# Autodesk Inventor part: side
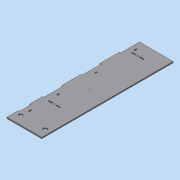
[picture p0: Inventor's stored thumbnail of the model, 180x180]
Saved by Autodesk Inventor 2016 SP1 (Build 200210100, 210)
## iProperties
Created: 2016-06
Part Number: side
Material: Generic
Document SubType Name: Modeling
Designer: Mohamed A.
Density: 1 g/cm^3
Appearance: Default
d0: 85.000 mm
d1: 320.000 mm
d2: 3.000 mm
d3: 0.00 deg
d6: 3.000 mm
d4: 233.000 mm
Author: Mohamed A.
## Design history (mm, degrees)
sketch "Sketch1"
  geometry: L1 (-42.5, 160)-(42.5, 160); L2 (42.5, 160)-(42.5, -160); L3 (42.5, -160)-(-42.5, -160); L4 (-42.5, -160)-(-42.5, 160); L5 (-42.5, 160)-(42.5, -160); L6 (42.5, 160)-(-42.5, -160); 1 further point
  constraints: 12 end point, 2 midpoint, 2 parallel, 1 horizontal, 1 perpendicular
  dimensions: "d0" = 85 distance of L2.end L3.end; "d1" = 320 distance of L1.end L2.end
extrude "Extrusion1" new body sketch "Sketch1" distance "d2" = 3; taper "d3" = 0 deg
sketch "Sketch2"
  geometry: L1 (-26.505, -73)-(-16.505, -73) reference; L2 (-7.505, -76)-(2.495, -76) reference; L3 (42.5, 160)-(-42.5, 160) reference; L4 (-42.5, 113.4)-(-39.5, 113.4); L5 (-39.5, 113.4)-(-39.5, 160); L6 (-42.5, 66.8)-(-39.5, 66.8); L7 (-39.5, 66.8)-(-39.5, 20.2); L8 (-39.5, 20.2)-(-42.5, 20.2); L9 (-39.5, -26.4)-(-42.5, -26.4); L10 (-42.5, -26.4)-(-42.5, -73); L11 (-39.5, 160)-(-42.5, 160); L12 (-42.5, 113.4)-(-42.5, 160); L13 (-42.5, 66.8)-(-42.5, 20.2); L14 (-39.5, -26.4)-(-39.5, -73); L15 (-42.5, -73)-(-39.5, -73); L16 (-42.5, -104)-(-39.5, -104); L17 (-39.5, -104)-(-39.5, -132); L18 (-39.5, -132)-(-42.5, -132); L19 (-42.5, -132)-(-42.5, -104); L20 (-42.5, -160)-(42.5, -160) reference; 1 further point; 1 other entity
  constraints: 32 end point, 6 perpendicular, 5 horizontal, 3 parallel, 2 point on line, 2 vertical, 1 collinear, 2 other
  dimensions: "d4" = 233 distance from line of L3 L1.start (derived); "d6" = 3 distance of L4.start L4.end; "d7" = 46.6 distance between parallel lines of L3 L4 (= 0.2 x d4); "d8" = 3 distance of L6.start L6.end; "d9" = 46.6 distance between parallel lines of L4 L6 (= d7); "d10" = 46.6 distance between parallel lines of L6 L8 (= d7); "d11" = 46.6 distance between parallel lines of L9 L8 (= d10); "d16" = 3 distance of L17.end L18.end; "d17" = 28 distance between parallel lines of L18 L16 (= 0.333333 x d18); "d18" = 84 distance between parallel lines of L20 L2 (derived); "d19" = 28 distance between parallel lines of L16 L2 (= d17); "d20" = 3 distance between parallel lines of L10 L14
extrude "Extrusion2" cut sketch "Sketch2" distance "d12" = 10; taper "d13" = 0 deg
sketch "Sketch3"
  geometry: L1 (-29.5, 142.2)-(-26.5, 142.2); L2 (-26.5, 142.2)-(-26.5, 136.2); L3 (-26.5, 136.2)-(-29.5, 136.2); L4 (-29.5, 136.2)-(-29.5, 142.2); L5 (-29.5, 45.05)-(-26.5, 45.05); L6 (-26.5, 45.05)-(-26.5, 40.5); L7 (-26.5, 40.5)-(-29.5, 40.5); L8 (-29.5, 40.5)-(-29.5, 45.05); L9 (-29.5, -46.7)-(-26.5, -46.7); L10 (-26.5, -46.7)-(-26.5, -52.7); L11 (-26.5, -52.7)-(-29.5, -52.7); L12 (-29.5, -52.7)-(-29.5, -46.7); L13 (-29.5, -115)-(-26.5, -115); L14 (-26.5, -115)-(-26.5, -121); L15 (-26.5, -121)-(-29.5, -121); L16 (-29.5, -121)-(-29.5, -115); L17 (-10.455, 130)-(-13.555, 130) reference; L18 (-10.455, 130)-(-10.455, 127) reference; L19 (-13.555, 127)-(-10.455, 127) reference; L20 (-13.555, 130)-(-13.555, 127) reference; L21 (-10.455, -73)-(-13.555, -73) reference; L22 (-10.455, -73)-(-10.455, -76) reference; L23 (-13.555, -76)-(-10.455, -76) reference; L24 (-13.555, -73)-(-13.555, -76) reference; L25 (-16.505, 130)-(-16.505, 127) reference; L26 (-16.505, 127)-(-26.505, 127) reference; L27 (-26.505, 127)-(-26.505, 130) reference; L28 (-26.505, 130)-(-16.505, 130) reference; L29 (-7.505, 127)-(-7.505, 130) reference; L30 (-7.505, 130)-(2.495, 130) reference; L31 (2.495, 130)-(2.495, 127) reference; L32 (2.495, 127)-(-7.505, 127) reference; L33 (2.495, -73)-(2.495, -76) reference; L34 (2.495, -76)-(-7.505, -76) reference; L35 (-7.505, -76)-(-7.505, -73) reference; L36 (-7.505, -73)-(2.495, -73) reference; L37 (-26.505, -76)-(-26.505, -73) reference; L38 (-26.505, -73)-(-16.505, -73) reference; L39 (-16.505, -73)-(-16.505, -76) reference; L40 (-16.505, -76)-(-26.505, -76) reference; L41 (-21, -118)-(-21, -160) reference; L42 (21, -160)-(21, -118) reference; C1 r 1.4 at (-12.005, 128.5); C2 r 1.4 at (-12.005, -74.5); C3 r 4.7 at (-29.7, -139); C4 r 4.7 at (29.7, -139); C5 r 8.05 at (0, -139) reference; C6 r 8.05 at (0, -139) reference; C7 r 9.05 at (0, -139); C8 r 2 at (0, -127.543) reference; C9 r 2 at (9.922, -144.728) reference; C10 r 2 at (-9.922, -144.728) reference; C11 r 1.4 at (0, -127.543); C12 r 1.4 at (9.922, -144.728); C13 r 1.4 at (-9.922, -144.728); 9 further points
  constraints: 64 end point, 12 horizontal, 8 centre point, 8 parallel, 8 vertical, 4 perpendicular, 3 coincident, 32 other
  dimensions: "d22" = 2.8 diameter of C1; "d23" = 2.8 diameter of C2; "d24" = 9.4 diameter of C3; "d25" = 8.7 distance from line of C3.centre L41; "d26" = 42 distance of L41.start L41.end (derived); "d27" = 21 vertical distance of C3.centre L41.start (= 0.5 x d26); "d28" = 9.4 diameter of C4; "d29" = 21 vertical distance of C4.centre L42.end; "d30" = 8.7 distance from line of L42 C4.centre (= d25); "d31" = 1 radial gap between concentric circles of C5 C7; "d32" = 2.8 diameter of C11; "d33" = 2.8 diameter of C12; "d34" = 2.8 diameter of C13
extrude "Extrusion3" cut sketch "Sketch3" distance "d14" = 10; taper "d15" = 0 deg
sketch "Sketch4"
  geometry: 1 further point
body "Solid1"
node "Reference3"
node "Reference4"
node "Reference5"
node "Reference6"
node "Reference7"
node "Reference8"
node "Reference9"
node "Reference10"
node "Reference11"
node "Reference12"
node "Reference13"
